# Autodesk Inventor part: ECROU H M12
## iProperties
Created: 2004-11
Part Number: ECROU H M12
Document SubType Name: Modeling
Designer: Bruno
Manufacturer: Standard
Standards Organization: Custom
Author: Bruno
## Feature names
1. Base1
